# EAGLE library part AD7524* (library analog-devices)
8-Bit Buffered Multiplying DAC Source: http://www.analog.com/UploadedFiles/Data_Sheets/888358036ad7524.pdf
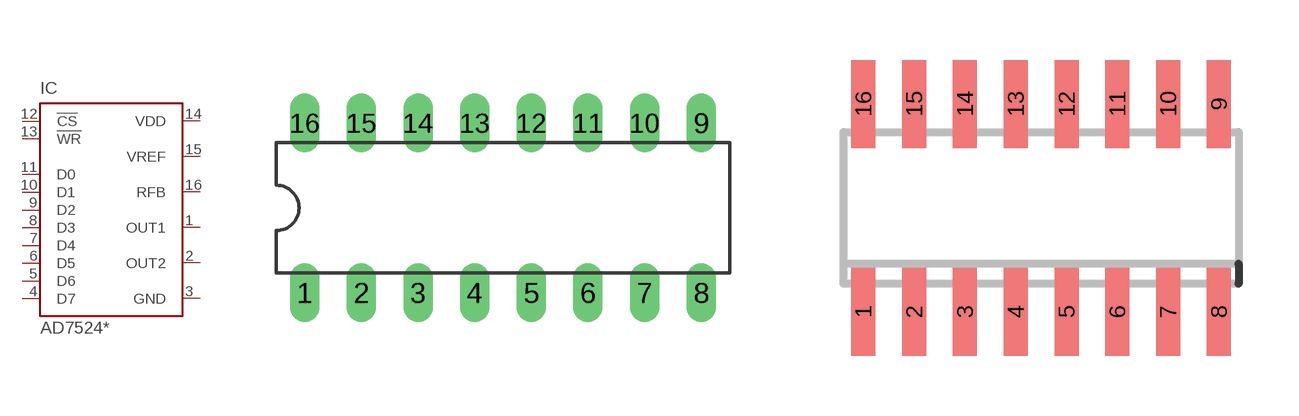
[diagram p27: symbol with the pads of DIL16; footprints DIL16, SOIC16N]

Designator prefix IC

## AD7524JN (MF: ALTERA CORPORATION; MPN: AD7524JNZ; OC_FARNELL: 9605401; OC_NEWARK: 59K4969), AD7524KN (MF: ALTERA CORPORATION; MPN: AD7524KNZ; OC_FARNELL: 1464568; OC_NEWARK: 59K4973), AD7524LN (MF: ALTERA CORPORATION; MPN: AD7524LNZ; OC_FARNELL: 9605401; OC_NEWARK: 59K4974)  [DIL16]
1  OUT1  pas
2  OUT2  pas
3  GND  pwr
4  D7  in
5  D6  in
6  D5  in
7  D4  in
8  D3  in
9  D2  in
10  D1  in
11  D0  in
12  !CS  in
13  !WR  in
14  VDD  pwr
15  VREF  in
16  RFB  pas

## AD7524JR (MF: ALTERA CORPORATION; MPN: AD7524JRZ; OC_FARNELL: 1423882; OC_NEWARK: 59K4970)  [SOIC16N]
Pads as for DIL16

## AD7524JP (MF: ALTERA CORPORATION; MPN: AD7524JP; OC_FARNELL: 1464569; OC_NEWARK: 05F7382), AD7524KP (OC_FARNELL: 1464569; OC_NEWARK: unknown), AD7524LP (MF: ALTERA CORPORATION; MPN: AD7524LP; OC_FARNELL: 1464569; OC_NEWARK: 09B5765)  [PLCC20]
2  OUT1  pas
3  OUT2  pas
4  GND  pwr
5  D7  in
7  D6  in
8  D5  in
9  D4  in
10  D3  in
12  D2  in
13  D1  in
14  D0  in
15  !CS  in
17  !WR  in
18  VDD  pwr
19  VREF  in
20  RFB  pas

## AD7524SE (MF: ALTERA CORPORATION; MPN: AD7524JP; OC_FARNELL: unknown; OC_NEWARK: 05F7382), AD7524TE (MF: ALTERA CORPORATION; MPN: AD7524JP; OC_FARNELL: 1464569; OC_NEWARK: 05F7382), AD7524UE (MF: ALTERA CORPORATION; MPN: AD7524KP; OC_FARNELL: 1464569; OC_NEWARK: 09B5764)  [LCC20]
Pads as for PLCC20

## AD7524AQ (MF: ALTERA CORPORATION; MPN: AD7524AQ; OC_FARNELL: 1464568; OC_NEWARK: 05F7379), AD7524BQ (MF: ALTERA CORPORATION; MPN: AD7524KP; OC_FARNELL: 9605401; OC_NEWARK: 09B5764), AD7524CQ (MF: ALTERA CORPORATION; MPN: AD7524TQ; OC_FARNELL: 1523901; OC_NEWARK: 16F3371), AD7524SQ (MF: ALTERA CORPORATION; MPN: AD7524SQ; OC_FARNELL: 9605401; OC_NEWARK: 16F3370), AD7524TQ (MF: ALTERA CORPORATION; MPN: AD7524TQ; OC_FARNELL: 9605401; OC_NEWARK: 16F3371), AD7524UQ (MF: ALTERA CORPORATION; MPN: AD7524SQ; OC_FARNELL: 1523901; OC_NEWARK: 16F3370)  [DIL16]
Pads as for DIL16

## Footprint DIL16 (pad centres in mm)
Dual In Line Package
drill 0.813 long: 1 -8.89,-3.81; 2 -6.35,-3.81; 3 -3.81,-3.81; 4 -1.27,-3.81; 5 1.27,-3.81; 6 3.81,-3.81; 7 6.35,-3.81; 8 8.89,-3.81; 9 8.89,3.81; 10 6.35,3.81; 11 3.81,3.81; 12 1.27,3.81; 13 -1.27,3.81; 14 -3.81,3.81; 15 -6.35,3.81; 16 -8.89,3.81

## Footprint SOIC16N (pad centres in mm)
SMALL OUTLINE INTEGRATED CIRCUIT
smd 0.6 x 2.2: 1 -4.445,-2.6; 2 -3.175,-2.6; 3 -1.905,-2.6; 4 -0.635,-2.6; 5 0.635,-2.6; 6 1.905,-2.6; 7 3.175,-2.6; 8 4.445,-2.6; 9 4.445,2.6; 10 3.175,2.6; 11 1.905,2.6; 12 0.635,2.6; 13 -0.635,2.6; 14 -1.905,2.6; 15 -3.175,2.6; 16 -4.445,2.6

## Footprint PLCC20 (pad centres in mm)
Plastic Leaded Chip Carrier IPC standard
smd 0.6 x 2.2: 1 0,4.3; 2 -1.27,4.3; 3 -2.54,4.3; 9 -2.54,-4.3; 10 -1.27,-4.3; 11 0,-4.3; 12 1.27,-4.3; 13 2.54,-4.3; 19 2.54,4.3; 20 1.27,4.3
smd 2.2 x 0.6: 4 -4.3,2.54; 5 -4.3,1.27; 6 -4.3,0; 7 -4.3,-1.27; 8 -4.3,-2.54; 14 4.3,-2.54; 15 4.3,-1.27; 16 4.3,0; 17 4.3,1.27; 18 4.3,2.54

## Footprint LCC20 (pad centres in mm)
PLASTIC LEADED CHIP CARRIER
smd 0.8 x 3.4: 1 0,3.8
smd 0.8 x 2: 2 -1.27,4.5; 3 -2.54,4.5; 9 -2.54,-4.5; 10 -1.27,-4.5; 11 0,-4.5; 12 1.27,-4.5; 13 2.54,-4.5; 19 2.54,4.5; 20 1.27,4.5
smd 2 x 0.8: 4 -4.5,2.54; 5 -4.5,1.27; 6 -4.5,0; 7 -4.5,-1.27; 8 -4.5,-2.54; 14 4.5,-2.54; 15 4.5,-1.27; 16 4.5,0; 17 4.5,1.27; 18 4.5,2.54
